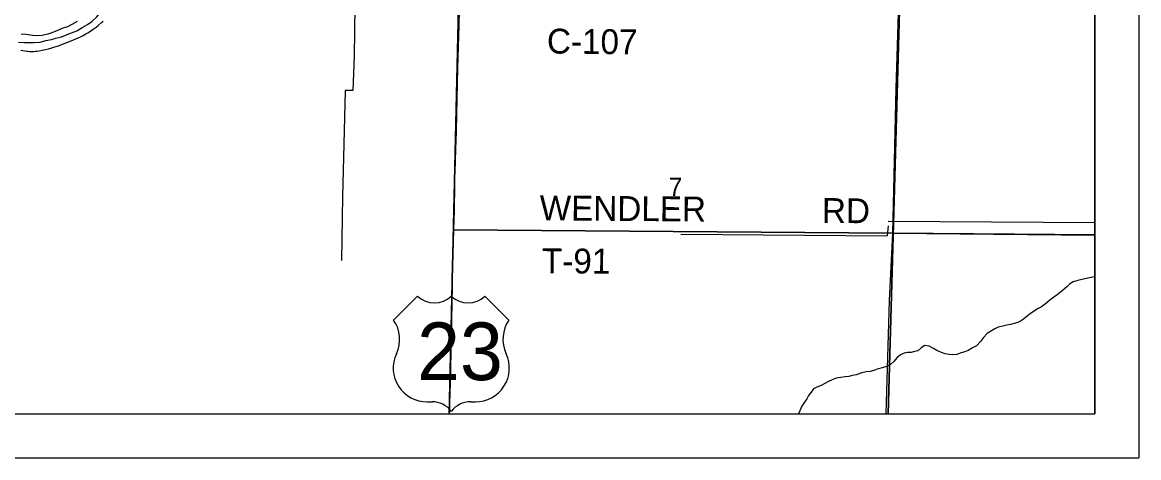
# Model space of a CAD drawing. Extents: x 0 to 34, y 0 to 22.
# Drawn here: x 6.448 to 9, y 14 to 14.995 of the extents above; entities that cross this region are included whole.
import ezdxf

# ---------------------------------------------------------------- set-up
doc = ezdxf.new("R2010")
doc.units = 0
for name, color, linetype in [('GM_X_City_Street', 7, 'Continuous'), ('GM_X_County_Road_Text', 7, 'Continuous'), ('GM_X_Major_River', 7, 'Continuous'), ('GM_X_Minor_River', 7, 'Continuous'), ('GM_X_Section_Text', 7, 'Continuous'), ('GM_X_Township_Road', 7, 'Continuous'), ('GM_X_Township_Road_Text', 7, 'Continuous'), ('GM_X_US_Location', 7, 'Continuous'), ('GM_X_US_Route', 7, 'Continuous'), ('GM_X_US_Shield', 7, 'Continuous'), ('SH_Cut_Line', 7, 'Continuous'), ('SH_Data', 7, 'Continuous')]:
    doc.layers.add(name, color=color, linetype=linetype)

msp = doc.modelspace()

# ---------------------------------------------------------------- linework, layer by layer
at = {"layer": 'GM_X_City_Street'}
for points in [[(7.4233, 14.1), (8.4275, 14.1), (8.4534, 15.0216), (7.4447, 15.0317), (7.4446, 15.029)], [(8.4275, 14.1), (8.9, 14.1), (8.9, 15.0171), (8.4534, 15.0216)]]:
    msp.add_lwpolyline(points, close=True, dxfattribs=at)
at = {"layer": 'GM_X_Major_River'}
for points in [[(6.4399, 14.9498), (6.4535, 14.9487), (6.4637, 14.9489), (6.4755, 14.9489), (6.4895, 14.9501), (6.5025, 14.9536), (6.515, 14.956), (6.5247, 14.9588), (6.5379, 14.9619), (6.5509, 14.9676), (6.5612, 14.9712), (6.5734, 14.9758), (6.5865, 14.9838), (6.5977, 14.9904), (6.6077, 14.997), (6.6185, 15.0077), (6.6275, 15.0181), (6.6385, 15.0319), (6.6448, 15.0447), (6.6482, 15.0567), (6.6508, 15.0703), (6.6522, 15.082), (6.654, 15.0922), (6.6554, 15.1051)], [(6.5736, 14.9967), (6.5613, 14.9901), (6.5517, 14.9847), (6.541, 14.9815), (6.5288, 14.9765), (6.5162, 14.9715), (6.5066, 14.9679), (6.494, 14.9652), (6.4798, 14.9645), (6.4714, 14.9654), (6.457, 14.9672), (6.4456, 14.9683)]]:
    msp.add_lwpolyline(points, dxfattribs=at)
at = {"layer": 'GM_X_Minor_River'}
for p, q in [((8.4272, 14.5298), (8.425, 14.5071)), ((8.9, 14.5371), (8.4272, 14.5401)), ((8.425, 14.5067), (7.9536, 14.5105))]:
    msp.add_line(p, q, dxfattribs=at)
for points in [[(7.2084, 15.0321), (7.2067, 14.9179), (7.204, 14.8394), (7.1862, 14.8391), (7.1832, 14.717), (7.1806, 14.5967), (7.1781, 14.451)], [(8.9, 14.4137), (8.8906, 14.4122), (8.8808, 14.4099), (8.8702, 14.4075), (8.8611, 14.4052), (8.8505, 14.4017), (8.8429, 14.3971), (8.8349, 14.3899), (8.8255, 14.3815), (8.8138, 14.3723), (8.8058, 14.367), (8.7971, 14.3597), (8.7869, 14.3513), (8.7778, 14.3448), (8.7687, 14.3406), (8.7608, 14.3352), (8.7524, 14.3299), (8.7449, 14.3234), (8.7369, 14.3165), (8.7275, 14.3107), (8.7188, 14.3073), (8.707, 14.3046), (8.6983, 14.3026), (8.6892, 14.3007), (8.679, 14.2983), (8.671, 14.2945), (8.6634, 14.2899), (8.654, 14.2838)], [(8.654, 14.2838), (8.6457, 14.2746), (8.6385, 14.2655), (8.6294, 14.2559), (8.6199, 14.2509), (8.6101, 14.2452), (8.6025, 14.2417), (8.5942, 14.2394), (8.5847, 14.236), (8.5749, 14.2348), (8.5665, 14.2359), (8.5581, 14.2377), (8.549, 14.2403), (8.5384, 14.2448), (8.5308, 14.2493), (8.5213, 14.2546), (8.5114, 14.2564), (8.5031, 14.2511), (8.4951, 14.2442), (8.4876, 14.2427), (8.48, 14.2407), (8.472, 14.2403), (8.4637, 14.2391), (8.4553, 14.2353), (8.447, 14.2284), (8.4413, 14.2204), (8.4326, 14.2128), (8.4236, 14.2085), (8.4137, 14.2054), (8.4023, 14.202), (8.3947, 14.1996), (8.386, 14.1973), (8.3769, 14.1961), (8.3675, 14.1942), (8.3546, 14.1896), (8.3455, 14.1876), (8.3375, 14.1853), (8.3295, 14.1845), (8.3189, 14.1833), (8.3083, 14.1817), (8.2992, 14.1779), (8.2909, 14.174), (8.2825, 14.1694), (8.2742, 14.1652), (8.2647, 14.161), (8.2568, 14.1575), (8.2511, 14.1499), (8.2455, 14.1419), (8.2413, 14.1343), (8.236, 14.1267), (8.2304, 14.1175), (8.2255, 14.1073), (8.2225, 14.1)]]:
    msp.add_lwpolyline(points, dxfattribs=at)
at = {"layer": 'GM_X_Township_Road'}
for points in [[(8.4384, 14.5129), (8.4459, 14.8437), (8.4514, 15.0162)], [(6.4451, 14.9313), (6.4539, 14.9298), (6.459, 14.9291), (6.4612, 14.929), (6.4652, 14.9287), (6.47, 14.9286), (6.4743, 14.9288), (6.4784, 14.9291), (6.482, 14.9296), (6.4872, 14.9303), (6.4941, 14.9316), (6.5014, 14.9331), (6.5084, 14.9348), (6.5157, 14.9368), (6.5231, 14.939), (6.5312, 14.9418), (6.54, 14.9449), (6.5501, 14.9488), (6.5599, 14.9526), (6.5708, 14.9572), (6.5798, 14.9613), (6.5877, 14.9652), (6.5939, 14.9687), (6.5994, 14.9719), (6.6051, 14.9756), (6.6103, 14.9792), (6.6147, 14.9823), (6.6171, 14.984), (6.6225, 14.9883), (6.6295, 14.9946), (6.6331, 14.998)], [(7.4343, 14.5207), (8.4384, 14.5129), (8.9, 14.5085)], [(8.4226, 14.1), (8.4303, 14.3594), (8.4384, 14.5129)]]:
    msp.add_lwpolyline(points, dxfattribs=at)
at = {"layer": 'GM_X_US_Route'}
for points in [[(7.4467, 15.0231), (7.4458, 14.9882), (7.4446, 14.94), (7.4434, 14.8903), (7.4407, 14.7862), (7.4397, 14.7458), (7.4387, 14.7054), (7.438, 14.6775), (7.4366, 14.6371), (7.4363, 14.6231), (7.4352, 14.5656), (7.4341, 14.5212), (8.4382, 14.5134), (8.9, 14.5091), (8.9, 20.9)], [(3.4084, 14.1), (7.4244, 14.1), (7.425, 14.1242), (7.4268, 14.1942), (7.4281, 14.2517), (7.4291, 14.3045), (7.4305, 14.3636), (7.4307, 14.3807), (7.4311, 14.404), (7.4311, 14.4071), (7.4326, 14.4661), (7.4341, 14.5212), (7.4352, 14.5656), (7.4363, 14.6231), (7.4366, 14.6371), (7.438, 14.6775), (7.4387, 14.7054), (7.4397, 14.7458), (7.4407, 14.7862), (7.4434, 14.8903), (7.4446, 14.94), (7.4458, 14.9882), (7.4467, 15.0231)], [(7.4343, 14.5207), (7.4355, 14.565), (7.4365, 14.6225), (7.4368, 14.6365), (7.4382, 14.6769), (7.4389, 14.7049), (7.4399, 14.7453), (7.4409, 14.7857), (7.4436, 14.8898), (7.4449, 14.9395), (7.4461, 14.9877), (7.447, 15.0225)], [(7.4246, 14.1), (7.4252, 14.1237), (7.4271, 14.1936), (7.4283, 14.2511), (7.4293, 14.304), (7.4307, 14.363), (7.4309, 14.3801), (7.4313, 14.4034), (7.4313, 14.4065), (7.4328, 14.4656), (7.4343, 14.5207)]]:
    msp.add_lwpolyline(points, dxfattribs=at)
msp.add_lwpolyline([(7.4244, 14.1), (8.9, 14.1), (8.9, 14.5091), (8.4382, 14.5134), (7.4341, 14.5212), (7.4326, 14.4661), (7.4311, 14.4071), (7.4311, 14.404), (7.4307, 14.3807), (7.4305, 14.3636), (7.4291, 14.3045), (7.4281, 14.2517), (7.4268, 14.1942), (7.425, 14.1242)], close=True, dxfattribs=at)
at = {"layer": 'GM_X_US_Shield'}
for p, q in [((7.352, 14.3695), (7.2971, 14.3146)), ((7.5608, 14.3146), (7.5058, 14.3695)), ((7.374, 14.1278), (7.385, 14.1278)), ((7.4729, 14.1278), (7.4839, 14.1278))]:
    msp.add_line(p, q, dxfattribs=at)
for centre, radius, start, end in [((7.3905, 14.4087), 0.0549, 225.573, 314.427), ((7.4674, 14.4087), 0.0549, 225.573, 314.427), ((7.2341, 14.2705), 0.0769, 334.5471, 35.0009), ((7.6238, 14.2705), 0.0769, 144.9991, 205.4529), ((7.3731, 14.2047), 0.0769, 154.8319, 270.6383), ((7.4847, 14.2047), 0.0769, 269.3617, 25.1681), ((7.385, 14.0729), 0.0549, 36.8699, 90), ((7.4729, 14.0729), 0.0549, 90, 143.1301)]:
    msp.add_arc(centre, radius, start, end, dxfattribs=at)
at = {"layer": 'SH_Cut_Line'}
for points in [[(7.4467, 15.0231), (7.4458, 14.9882), (7.4446, 14.94), (7.4434, 14.8903), (7.4407, 14.7862), (7.4397, 14.7458), (7.4387, 14.7054), (7.438, 14.6775), (7.4366, 14.6371), (7.4363, 14.6231), (7.4352, 14.5656), (7.4341, 14.5212), (7.4326, 14.4661), (7.4311, 14.4071), (7.4311, 14.404), (7.4307, 14.3807), (7.4305, 14.3636), (7.4291, 14.3045), (7.4281, 14.2517), (7.4268, 14.1942), (7.425, 14.1242), (7.4244, 14.1), (8.9, 14.1), (8.9, 20.9)], [(2.1, 14.1), (7.4244, 14.1), (7.425, 14.1242), (7.4268, 14.1942), (7.4281, 14.2517), (7.4291, 14.3045), (7.4305, 14.3636), (7.4307, 14.3807), (7.4311, 14.404), (7.4311, 14.4071), (7.4326, 14.4661), (7.4341, 14.5212), (7.4352, 14.5656), (7.4363, 14.6231), (7.4366, 14.6371), (7.438, 14.6775), (7.4387, 14.7054), (7.4397, 14.7458), (7.4407, 14.7862), (7.4434, 14.8903), (7.4446, 14.94), (7.4458, 14.9882), (7.4467, 15.0231)]]:
    msp.add_lwpolyline(points, dxfattribs=at)
at = {"layer": 'SH_Data'}
for p, q in [((9, 21), (9, 14)), ((8.9, 20.9), (8.9, 14.1)), ((2.1, 14.1), (8.9, 14.1)), ((2, 14), (9, 14))]:
    msp.add_line(p, q, dxfattribs=at)

# ---------------------------------------------------------------- texts
at = {"layer": 'GM_X_County_Road_Text'}
msp.add_text('C-107', height=0.05682, rotation=359.4494, dxfattribs=at).set_placement((7.6473, 14.924))
at = {"layer": 'GM_X_Section_Text'}
msp.add_text('7', height=0.0419, rotation=0, dxfattribs=at).set_placement((7.9257, 14.5979))
at = {"layer": 'GM_X_Township_Road_Text'}
for s, rotation, p in [('WENDLER', 359.5774, (7.6309, 14.5426)), ('RD', 359.5045, (8.2759, 14.5367)), ('T-91', 359.6452, (7.636, 14.4216))]:
    msp.add_text(s, height=0.05682, rotation=rotation, dxfattribs=at).set_placement(p)
at = {"layer": 'GM_X_US_Location'}
for s in ['0', '/']:
    msp.add_text(s, height=0.000189, dxfattribs=at).set_placement((7.4289, 14.2421))
msp.add_text('23', height=0.000189, rotation=0, dxfattribs=at).set_placement((7.3898, 14.2029))
at = {"layer": 'GM_X_US_Shield'}
msp.add_text('23', height=0.13184, dxfattribs=at).set_placement((7.3507, 14.1772))

doc.saveas('drawing.dxf')
